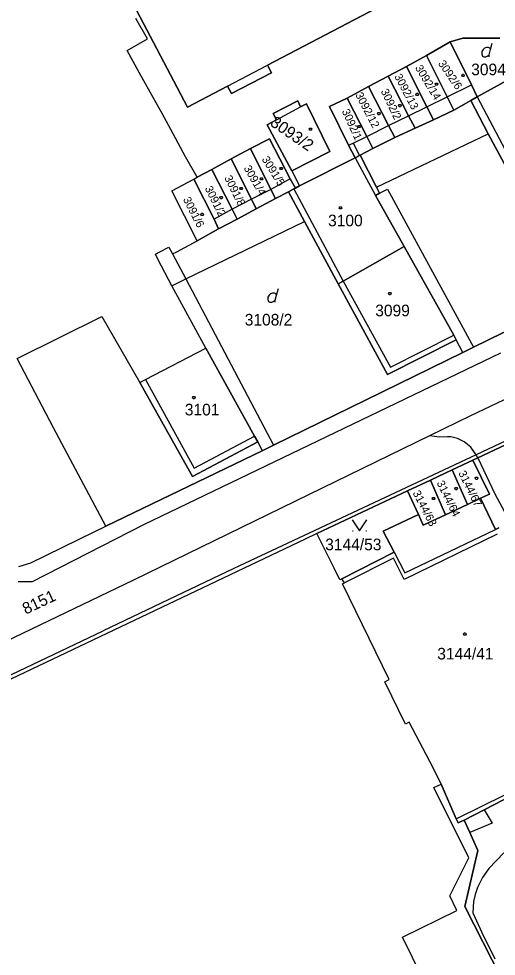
# Model space of a CAD drawing. Extents: x -263587 to -261993, y -1238795 to -1236748.
# Drawn here: x -263095.1 to -263029.4, y -1238503 to -1238374.1 of the extents above; entities that cross this region are included whole.
import ezdxf

# ---------------------------------------------------------------- set-up
doc = ezdxf.new("R2010")
doc.units = 0
doc.layers.add('Vrstva 1', color=7, linetype='Continuous')

msp = doc.modelspace()

# ---------------------------------------------------------------- linework, layer by layer
at = {"layer": 'Vrstva 1'}
for p, q in [((-263079.94, -1238370.91), (-263071.91, -1238386.25)), ((-263071.91, -1238386.25), (-263079.94, -1238370.91)), ((-263060.89, -1238380.49), (-263044.93, -1238372.15)), ((-263044.93, -1238372.15), (-263060.89, -1238380.49)), ((-263077.39, -1238376.88), (-263078.98, -1238374.05)), ((-263080.18, -1238378.46), (-263077.39, -1238376.88)), ((-263035.8, -1238377.26), (-263039.04, -1238379.17)), ((-263039.04, -1238379.17), (-263035.8, -1238377.26)), ((-263035.8, -1238377.26), (-263034.03, -1238376.76)), ((-263034.03, -1238376.76), (-263035.8, -1238377.26)), ((-263032.83, -1238383.17), (-263035.8, -1238377.26)), ((-263035.8, -1238377.26), (-263032.83, -1238383.17)), ((-263034.03, -1238376.76), (-263028.94, -1238376.78)), ((-263028.94, -1238376.78), (-263034.03, -1238376.76)), ((-263078.54, -1238381.47), (-263080.18, -1238378.46)), ((-263030.26, -1238378.34), (-263029.99, -1238377.44)), ((-263039.04, -1238379.17), (-263041.79, -1238380.66)), ((-263041.79, -1238380.66), (-263039.04, -1238379.17)), ((-263039.04, -1238379.17), (-263036.22, -1238384.84)), ((-263036.22, -1238384.84), (-263039.04, -1238379.17)), ((-263066.38, -1238383.36), (-263060.89, -1238380.49)), ((-263060.34, -1238381.53), (-263060.89, -1238380.49)), ((-263060.89, -1238380.49), (-263060.34, -1238381.53)), ((-263041.79, -1238380.66), (-263044.33, -1238382)), ((-263044.33, -1238382), (-263041.79, -1238380.66)), ((-263039, -1238386.21), (-263041.79, -1238380.66)), ((-263041.79, -1238380.66), (-263039, -1238386.21)), ((-263032.07, -1238384.84), (-263024.15, -1238380.47)), ((-263024.15, -1238380.47), (-263032.07, -1238384.84)), ((-263077.04, -1238384.18), (-263078.54, -1238381.47)), ((-263065.83, -1238384.4), (-263060.34, -1238381.53)), ((-263060.34, -1238381.53), (-263065.83, -1238384.4)), ((-263044.33, -1238382), (-263047.02, -1238383.41)), ((-263047.02, -1238383.41), (-263044.33, -1238382)), ((-263041.51, -1238387.44), (-263044.33, -1238382)), ((-263044.33, -1238382), (-263041.51, -1238387.44)), ((-263071.91, -1238386.25), (-263066.38, -1238383.36)), ((-263066.38, -1238383.36), (-263071.91, -1238386.25)), ((-263066.38, -1238383.36), (-263065.83, -1238384.4)), ((-263065.83, -1238384.4), (-263066.38, -1238383.36)), ((-263047.02, -1238383.41), (-263049.93, -1238385.01)), ((-263049.93, -1238385.01), (-263047.02, -1238383.41)), ((-263047.02, -1238383.41), (-263044.26, -1238388.79)), ((-263044.26, -1238388.79), (-263047.02, -1238383.41)), ((-263036.22, -1238384.84), (-263032.83, -1238383.17)), ((-263032.07, -1238384.84), (-263032.83, -1238383.17)), ((-263032.83, -1238383.17), (-263032.07, -1238384.84)), ((-263075.4, -1238387.15), (-263077.04, -1238384.18)), ((-263049.93, -1238385.01), (-263052.38, -1238386.17)), ((-263052.38, -1238386.17), (-263049.93, -1238385.01)), ((-263047.26, -1238390.27), (-263049.93, -1238385.01)), ((-263049.93, -1238385.01), (-263047.26, -1238390.27)), ((-263039, -1238386.21), (-263036.22, -1238384.84)), ((-263036.22, -1238384.84), (-263035.3, -1238386.69)), ((-263035.3, -1238386.69), (-263036.22, -1238384.84)), ((-263032.93, -1238385.36), (-263032.07, -1238384.84)), ((-263032.07, -1238384.84), (-263032.93, -1238385.36)), ((-263032.07, -1238384.84), (-263025.51, -1238397.32)), ((-263060.1, -1238387.14), (-263056.74, -1238385.4)), ((-263056.74, -1238385.4), (-263060.1, -1238387.14)), ((-263059.65, -1238387.98), (-263056.36, -1238386.19)), ((-263056.74, -1238385.4), (-263056.36, -1238386.19)), ((-263056.36, -1238386.19), (-263056.74, -1238385.4)), ((-263056.36, -1238386.19), (-263055.53, -1238385.8)), ((-263055.53, -1238385.8), (-263056.36, -1238386.19)), ((-263055.53, -1238385.8), (-263052.35, -1238392.35)), ((-263052.35, -1238392.35), (-263055.53, -1238385.8)), ((-263052.38, -1238386.17), (-263049.75, -1238391.48)), ((-263049.75, -1238391.48), (-263052.38, -1238386.17)), ((-263041.51, -1238387.44), (-263039, -1238386.21)), ((-263038.1, -1238388.01), (-263039, -1238386.21)), ((-263039, -1238386.21), (-263038.1, -1238388.01)), ((-263035.3, -1238386.69), (-263032.93, -1238385.36)), ((-263032.93, -1238385.36), (-263035.3, -1238386.69)), ((-263032.93, -1238385.36), (-263030.56, -1238389.91)), ((-263030.56, -1238389.91), (-263032.93, -1238385.36)), ((-263073.86, -1238389.91), (-263075.4, -1238387.15)), ((-263059.65, -1238387.98), (-263060.1, -1238387.14)), ((-263060.1, -1238387.14), (-263059.65, -1238387.98)), ((-263044.26, -1238388.79), (-263041.51, -1238387.44)), ((-263040.61, -1238389.16), (-263041.51, -1238387.44)), ((-263041.51, -1238387.44), (-263040.61, -1238389.16)), ((-263038.1, -1238388.01), (-263035.3, -1238386.69)), ((-263035.3, -1238386.69), (-263038.1, -1238388.01)), ((-263060.95, -1238388.67), (-263059.65, -1238387.98)), ((-263059.65, -1238387.98), (-263060.95, -1238388.67)), ((-263057.55, -1238395.02), (-263060.95, -1238388.67)), ((-263060.95, -1238388.67), (-263057.55, -1238395.02)), ((-263047.26, -1238390.27), (-263044.26, -1238388.79)), ((-263044.26, -1238388.79), (-263043.41, -1238390.45)), ((-263043.41, -1238390.45), (-263044.26, -1238388.79)), ((-263040.61, -1238389.16), (-263038.1, -1238388.01)), ((-263038.1, -1238388.01), (-263040.61, -1238389.16)), ((-263072.18, -1238393.07), (-263073.86, -1238389.91)), ((-263045.9, -1238397.25), (-263030.56, -1238389.91)), ((-263043.41, -1238390.45), (-263040.61, -1238389.16)), ((-263040.61, -1238389.16), (-263043.41, -1238390.45)), ((-263030.56, -1238389.91), (-263026.36, -1238397.77)), ((-263026.36, -1238397.77), (-263030.56, -1238389.91)), ((-263060.61, -1238390.6), (-263063.22, -1238391.94)), ((-263063.22, -1238391.94), (-263060.61, -1238390.6)), ((-263057.79, -1238396.13), (-263060.61, -1238390.6)), ((-263060.61, -1238390.6), (-263057.79, -1238396.13)), ((-263049.75, -1238391.48), (-263049.13, -1238391.19)), ((-263049.13, -1238391.19), (-263047.26, -1238390.27)), ((-263049.13, -1238391.19), (-263048.26, -1238392.91)), ((-263046.4, -1238391.96), (-263047.26, -1238390.27)), ((-263047.26, -1238390.27), (-263046.4, -1238391.96)), ((-263046.4, -1238391.96), (-263043.41, -1238390.45)), ((-263043.41, -1238390.45), (-263046.4, -1238391.96)), ((-263063.22, -1238391.94), (-263065.89, -1238393.35)), ((-263065.89, -1238393.35), (-263063.22, -1238391.94)), ((-263060.44, -1238397.56), (-263063.22, -1238391.94)), ((-263063.22, -1238391.94), (-263060.44, -1238397.56)), ((-263052.35, -1238392.35), (-263057.55, -1238395.02)), ((-263057.55, -1238395.02), (-263052.35, -1238392.35)), ((-263049.75, -1238391.48), (-263048.86, -1238393.24)), ((-263048.86, -1238393.24), (-263049.75, -1238391.48)), ((-263048.14, -1238392.85), (-263046.4, -1238391.96)), ((-263046.4, -1238391.96), (-263048.14, -1238392.85)), ((-263070.58, -1238395.89), (-263072.18, -1238393.07)), ((-263065.89, -1238393.35), (-263068.56, -1238394.81)), ((-263068.56, -1238394.81), (-263065.89, -1238393.35)), ((-263065.89, -1238393.35), (-263063.08, -1238398.91)), ((-263063.08, -1238398.91), (-263065.89, -1238393.35)), ((-263056.52, -1238397.07), (-263048.86, -1238393.24)), ((-263048.86, -1238393.24), (-263056.52, -1238397.07)), ((-263048.86, -1238393.24), (-263048.26, -1238392.91)), ((-263048.26, -1238392.91), (-263048.86, -1238393.24)), ((-263048.86, -1238393.24), (-263046.07, -1238398.39)), ((-263048.26, -1238392.91), (-263048.14, -1238392.85)), ((-263048.14, -1238392.85), (-263048.26, -1238392.91)), ((-263045.9, -1238397.25), (-263048.14, -1238392.85)), ((-263048.14, -1238392.85), (-263045.9, -1238397.25)), ((-263068.56, -1238394.81), (-263070.58, -1238395.89)), ((-263070.58, -1238395.89), (-263068.56, -1238394.81)), ((-263065.75, -1238400.3), (-263068.56, -1238394.81)), ((-263068.56, -1238394.81), (-263065.75, -1238400.3)), ((-263057.55, -1238395.02), (-263056.52, -1238397.07)), ((-263074.04, -1238397.77), (-263071.03, -1238396.14)), ((-263071.03, -1238396.14), (-263070.58, -1238395.89)), ((-263071.03, -1238396.14), (-263068.25, -1238401.66)), ((-263068.25, -1238401.66), (-263071.03, -1238396.14)), ((-263057.79, -1238396.13), (-263060.44, -1238397.56)), ((-263057.07, -1238397.39), (-263057.79, -1238396.13)), ((-263057.79, -1238396.13), (-263057.07, -1238397.39)), ((-263070.59, -1238404.62), (-263074.04, -1238397.77)), ((-263060.44, -1238397.56), (-263063.08, -1238398.91)), ((-263059.82, -1238398.8), (-263060.44, -1238397.56)), ((-263060.44, -1238397.56), (-263059.82, -1238398.8)), ((-263059.82, -1238398.8), (-263058.03, -1238397.92)), ((-263058.03, -1238397.92), (-263059.82, -1238398.8)), ((-263058.03, -1238397.92), (-263057.29, -1238397.49)), ((-263057.29, -1238397.49), (-263058.03, -1238397.92)), ((-263058.03, -1238397.92), (-263055.82, -1238402)), ((-263055.82, -1238402), (-263058.03, -1238397.92)), ((-263057.29, -1238397.49), (-263057.07, -1238397.39)), ((-263057.07, -1238397.39), (-263057.29, -1238397.49)), ((-263057.29, -1238397.49), (-263050.48, -1238410.16)), ((-263057.07, -1238397.39), (-263056.52, -1238397.07)), ((-263056.52, -1238397.07), (-263057.07, -1238397.39)), ((-263045.5, -1238398.07), (-263045.9, -1238397.25)), ((-263045.9, -1238397.25), (-263045.5, -1238398.07)), ((-263045.5, -1238398.07), (-263044.4, -1238397.55)), ((-263044.4, -1238397.55), (-263032.6, -1238419.26)), ((-263063.08, -1238398.91), (-263065.75, -1238400.3)), ((-263063.08, -1238398.91), (-263062.47, -1238400.23)), ((-263062.47, -1238400.23), (-263063.08, -1238398.91)), ((-263062.47, -1238400.23), (-263059.82, -1238398.8)), ((-263059.82, -1238398.8), (-263062.47, -1238400.23)), ((-263046.07, -1238398.39), (-263045.5, -1238398.07)), ((-263045.5, -1238398.07), (-263046.07, -1238398.39)), ((-263042.13, -1238405.41), (-263046.07, -1238398.39)), ((-263046.07, -1238398.39), (-263042.13, -1238405.41)), ((-263065.75, -1238400.3), (-263068.25, -1238401.66)), ((-263065.09, -1238401.64), (-263065.75, -1238400.3)), ((-263065.75, -1238400.3), (-263065.09, -1238401.64)), ((-263065.09, -1238401.64), (-263062.47, -1238400.23)), ((-263062.47, -1238400.23), (-263065.09, -1238401.64)), ((-263068.25, -1238401.66), (-263067.63, -1238403)), ((-263067.63, -1238403), (-263068.25, -1238401.66)), ((-263067.63, -1238403), (-263065.09, -1238401.64)), ((-263065.09, -1238401.64), (-263067.63, -1238403)), ((-263072.15, -1238409.87), (-263055.82, -1238402)), ((-263070.59, -1238404.62), (-263067.63, -1238403)), ((-263067.63, -1238403), (-263070.59, -1238404.62)), ((-263055.82, -1238402), (-263051.2, -1238410.54)), ((-263051.2, -1238410.54), (-263055.82, -1238402)), ((-263075.69, -1238406.13), (-263074.48, -1238405.5)), ((-263074.48, -1238405.5), (-263073.94, -1238406.44)), ((-263073.36, -1238406.14), (-263070.59, -1238404.62)), ((-263042.13, -1238405.41), (-263050.48, -1238410.16)), ((-263050.48, -1238410.16), (-263042.13, -1238405.41)), ((-263035.3, -1238417.59), (-263042.13, -1238405.41)), ((-263042.13, -1238405.41), (-263035.3, -1238417.59)), ((-263076.28, -1238406.49), (-263075.69, -1238406.13)), ((-263075.91, -1238407.23), (-263076.28, -1238406.49)), ((-263073.94, -1238406.44), (-263073.36, -1238406.14)), ((-263073.94, -1238406.44), (-263072.15, -1238409.87)), ((-263074.05, -1238410.83), (-263075.91, -1238407.23)), ((-263009.51, -1238407.99), (-263032.6, -1238419.26)), ((-263032.6, -1238419.26), (-263009.51, -1238407.99)), ((-263074.05, -1238410.83), (-263072.15, -1238409.87)), ((-263072.15, -1238409.87), (-263060.09, -1238432.72)), ((-263050.48, -1238410.16), (-263051.2, -1238410.54)), ((-263051.2, -1238410.54), (-263050.48, -1238410.16)), ((-263051.2, -1238410.54), (-263044.42, -1238423.03)), ((-263044.42, -1238423.03), (-263051.2, -1238410.54)), ((-263050.48, -1238410.16), (-263043.99, -1238421.99)), ((-263069.38, -1238419.39), (-263074.05, -1238410.83)), ((-263059.67, -1238412.09), (-263059.4, -1238411.19)), ((-263095.34, -1238420.82), (-263083.68, -1238415.06)), ((-263083.68, -1238415.06), (-263078.47, -1238424.12)), ((-263044.42, -1238423.03), (-263034.94, -1238418.24)), ((-263034.94, -1238418.24), (-263044.42, -1238423.03)), ((-263043.99, -1238421.99), (-263035.3, -1238417.59)), ((-263034.94, -1238418.24), (-263035.3, -1238417.59)), ((-263035.3, -1238417.59), (-263034.94, -1238418.24)), ((-263034.05, -1238420), (-263034.94, -1238418.24)), ((-263077.67, -1238423.72), (-263069.38, -1238419.39)), ((-263062.69, -1238431.48), (-263069.38, -1238419.39)), ((-263069.38, -1238419.39), (-263062.69, -1238431.48)), ((-263032.6, -1238419.26), (-263034.05, -1238420)), ((-263034.05, -1238420), (-263032.6, -1238419.26)), ((-263090.32, -1238430.33), (-263095.34, -1238420.82)), ((-263028.88, -1238420.08), (-263077.95, -1238443.69)), ((-263034.05, -1238420), (-263047.32, -1238426.49)), ((-263047.32, -1238426.49), (-263034.05, -1238420)), ((-263078.47, -1238424.12), (-263077.67, -1238423.72)), ((-263078.47, -1238424.12), (-263071.21, -1238437.03)), ((-263071.21, -1238437.03), (-263078.47, -1238424.12)), ((-263077.67, -1238423.72), (-263070.96, -1238435.89)), ((-263026.6, -1238425.67), (-263033.01, -1238428.71)), ((-263047.32, -1238426.49), (-263060.09, -1238432.72)), ((-263060.09, -1238432.72), (-263047.32, -1238426.49)), ((-263033.01, -1238428.71), (-263038.64, -1238431.46)), ((-263083.13, -1238443.86), (-263090.32, -1238430.33)), ((-263038.64, -1238431.46), (-263079.32, -1238451.28)), ((-263071.21, -1238437.03), (-263062.25, -1238432.28)), ((-263062.25, -1238432.28), (-263071.21, -1238437.03)), ((-263070.96, -1238435.89), (-263062.69, -1238431.48)), ((-263062.25, -1238432.28), (-263062.69, -1238431.48)), ((-263062.69, -1238431.48), (-263062.25, -1238432.28)), ((-263062.25, -1238432.28), (-263061.65, -1238433.5)), ((-263060.09, -1238432.72), (-263061.65, -1238433.5)), ((-263061.65, -1238433.5), (-263060.09, -1238432.72)), ((-263037.27, -1238431.63), (-263038.64, -1238431.46)), ((-263036.16, -1238431.58), (-263037.27, -1238431.63)), ((-263035.7, -1238431.6), (-263036.16, -1238431.58)), ((-263034.78, -1238431.81), (-263035.7, -1238431.6)), ((-263033.88, -1238432.25), (-263034.78, -1238431.81)), ((-263032.94, -1238433.01), (-263033.88, -1238432.25)), ((-263027.35, -1238431.78), (-263032.2, -1238434.06)), ((-263027.39, -1238432.34), (-263032, -1238434.48)), ((-263032, -1238434.48), (-263027.39, -1238432.34)), ((-263061.65, -1238433.5), (-263083.13, -1238443.86)), ((-263083.13, -1238443.86), (-263061.65, -1238433.5)), ((-263032.2, -1238434.06), (-263032.94, -1238433.01)), ((-263032.2, -1238434.06), (-263065.54, -1238449.71)), ((-263035.52, -1238436.14), (-263032.65, -1238434.78)), ((-263032.65, -1238434.78), (-263035.52, -1238436.14)), ((-263032, -1238434.48), (-263032.65, -1238434.78)), ((-263032.65, -1238434.78), (-263032, -1238434.48)), ((-263032.65, -1238434.78), (-263030.37, -1238439.45)), ((-263030.37, -1238439.45), (-263032.65, -1238434.78)), ((-263032, -1238434.48), (-263032.2, -1238434.06)), ((-263032, -1238434.48), (-263029.63, -1238439.4)), ((-263038.51, -1238437.53), (-263035.52, -1238436.14)), ((-263035.52, -1238436.14), (-263038.51, -1238437.53)), ((-263033.39, -1238440.87), (-263035.52, -1238436.14)), ((-263035.52, -1238436.14), (-263033.39, -1238440.87)), ((-263041.63, -1238439.03), (-263038.51, -1238437.53)), ((-263038.51, -1238437.53), (-263041.63, -1238439.03)), ((-263036.44, -1238442.31), (-263038.51, -1238437.53)), ((-263038.51, -1238437.53), (-263036.44, -1238442.31)), ((-263054.1, -1238444.88), (-263041.63, -1238439.03)), ((-263041.63, -1238439.03), (-263054.1, -1238444.88)), ((-263040.16, -1238442.27), (-263041.63, -1238439.03)), ((-263041.63, -1238439.03), (-263040.16, -1238442.27)), ((-263031.61, -1238440.03), (-263033.39, -1238440.87)), ((-263033.39, -1238440.87), (-263031.61, -1238440.03)), ((-263030.37, -1238439.45), (-263031.61, -1238440.03)), ((-263031.61, -1238440.03), (-263030.37, -1238439.45)), ((-263031.61, -1238440.03), (-263029.55, -1238444.33)), ((-263029.55, -1238444.33), (-263031.61, -1238440.03)), ((-263029.63, -1238439.4), (-263015.83, -1238465.48)), ((-263033.39, -1238440.87), (-263036.44, -1238442.31)), ((-263036.44, -1238442.31), (-263033.39, -1238440.87)), ((-263040.16, -1238442.27), (-263045.01, -1238444.54)), ((-263045.01, -1238444.54), (-263040.16, -1238442.27)), ((-263039.49, -1238443.75), (-263040.16, -1238442.27)), ((-263040.16, -1238442.27), (-263039.49, -1238443.75)), ((-263036.44, -1238442.31), (-263039.49, -1238443.75)), ((-263039.49, -1238443.75), (-263036.44, -1238442.31)), ((-263077.95, -1238443.69), (-263093.27, -1238451.5)), ((-263084.73, -1238444.64), (-263083.13, -1238443.86)), ((-263029.55, -1238444.33), (-263029.08, -1238444.1)), ((-263029.08, -1238444.1), (-263029.55, -1238444.33)), ((-263093.44, -1238448.92), (-263084.73, -1238444.64)), ((-263054.1, -1238444.88), (-263055.73, -1238445.65)), ((-263051.74, -1238449.65), (-263054.1, -1238444.88)), ((-263049.2, -1238444.52), (-263049.1, -1238444.52)), ((-263047.4, -1238444.52), (-263047.3, -1238444.52)), ((-263045.01, -1238444.54), (-263043.49, -1238447.45)), ((-263043.49, -1238447.45), (-263045.01, -1238444.54)), ((-263029.33, -1238444.95), (-263042.11, -1238451.22)), ((-263042, -1238450.3), (-263029.55, -1238444.33)), ((-263055.73, -1238445.65), (-263108.72, -1238470.85)), ((-263043.49, -1238447.45), (-263050.66, -1238451.1)), ((-263050.66, -1238451.1), (-263043.49, -1238447.45)), ((-263043.49, -1238447.45), (-263042, -1238450.3)), ((-263095.11, -1238449.43), (-263093.44, -1238448.92)), ((-263043.57, -1238448.28), (-263050.31, -1238451.68)), ((-263042.11, -1238451.22), (-263043.57, -1238448.28)), ((-263065.54, -1238449.71), (-263083.48, -1238458.24)), ((-263050.96, -1238451.25), (-263051.74, -1238449.65)), ((-263079.32, -1238451.28), (-263125.04, -1238473.29)), ((-263093.27, -1238451.5), (-263095.19, -1238451.53)), ((-263050.66, -1238451.1), (-263050.96, -1238451.25)), ((-263050.31, -1238451.68), (-263050.66, -1238451.1)), ((-263050.57, -1238451.79), (-263050.31, -1238451.68)), ((-263044.15, -1238464.94), (-263050.57, -1238451.79)), ((-263108.96, -1238470.41), (-263083.48, -1238458.24)), ((-263044.75, -1238465.28), (-263044.15, -1238464.94)), ((-263041.93, -1238471.08), (-263044.75, -1238465.28)), ((-263041.43, -1238470.82), (-263041.93, -1238471.08)), ((-263038.12, -1238477.11), (-263041.43, -1238470.82)), ((-263037.03, -1238479.33), (-263038.12, -1238477.11)), ((-263038.01, -1238479.81), (-263037.03, -1238479.33)), ((-263033.21, -1238489.48), (-263038.01, -1238479.81)), ((-263034.96, -1238484.09), (-263037.03, -1238479.33)), ((-263037.03, -1238479.33), (-263034.96, -1238484.09)), ((-263034.96, -1238484.09), (-263028.19, -1238480.77)), ((-263027.2, -1238480.85), (-263031.09, -1238482.85)), ((-263031.09, -1238482.85), (-263027.2, -1238480.85)), ((-263031.09, -1238482.85), (-263033.87, -1238484.27)), ((-263033.87, -1238484.27), (-263031.09, -1238482.85)), ((-263031.09, -1238482.85), (-263030.03, -1238484.71)), ((-263034.68, -1238484.65), (-263034.96, -1238484.09)), ((-263034.96, -1238484.09), (-263034.68, -1238484.65)), ((-263033.87, -1238484.27), (-263034.52, -1238484.59)), ((-263034.52, -1238484.59), (-263033.87, -1238484.27)), ((-263033.87, -1238484.27), (-263033.08, -1238486.01)), ((-263033.08, -1238486.01), (-263033.87, -1238484.27)), ((-263034.52, -1238484.59), (-263034.68, -1238484.65)), ((-263034.68, -1238484.65), (-263034.52, -1238484.59)), ((-263030.03, -1238484.71), (-263033.08, -1238486.01)), ((-263033.08, -1238486.01), (-263031.96, -1238488.46)), ((-263031.96, -1238488.46), (-263033.08, -1238486.01)), ((-263031.96, -1238488.46), (-263033.76, -1238496.15)), ((-263033.76, -1238496.15), (-263031.96, -1238488.46)), ((-263028.41, -1238488.79), (-263030.47, -1238490.94)), ((-263035.85, -1238494.71), (-263033.21, -1238489.48)), ((-263030.47, -1238490.94), (-263031.35, -1238492.18)), ((-263031.35, -1238492.18), (-263032.02, -1238493.53)), ((-263032.36, -1238494.5), (-263032.59, -1238495.49)), ((-263032.02, -1238493.53), (-263032.36, -1238494.5)), ((-263034.87, -1238496.72), (-263035.85, -1238494.71)), ((-263032.59, -1238495.49), (-263032.69, -1238497.05)), ((-263042.35, -1238500.36), (-263034.87, -1238496.72)), ((-263033.76, -1238496.15), (-263026.65, -1238510.12)), ((-263026.65, -1238510.12), (-263033.76, -1238496.15)), ((-263032.69, -1238497.05), (-263031.44, -1238499.76)), ((-263034.75, -1238515.65), (-263042.35, -1238500.36)), ((-263031.44, -1238499.76), (-263029.65, -1238503.37))]:
    msp.add_line(p, q, dxfattribs=at)
for points in [[(-263030.44, -1238379.33), (-263030.44, -1238379.06), (-263030.26, -1238378.34), (-263030.35, -1238378.16), (-263030.53, -1238378.07), (-263030.8, -1238378.07), (-263031.07, -1238378.16), (-263031.25, -1238378.34), (-263031.43, -1238378.61), (-263031.43, -1238378.97), (-263031.34, -1238379.24), (-263031.16, -1238379.33), (-263030.89, -1238379.33), (-263030.71, -1238379.24), (-263030.44, -1238379.06)], [(-263059.85, -1238413.08), (-263059.85, -1238412.81), (-263059.67, -1238412.09), (-263059.76, -1238411.91), (-263059.94, -1238411.82), (-263060.21, -1238411.82), (-263060.48, -1238411.91), (-263060.66, -1238412.09), (-263060.84, -1238412.36), (-263060.84, -1238412.72), (-263060.75, -1238412.99), (-263060.57, -1238413.08), (-263060.3, -1238413.08), (-263060.12, -1238412.99), (-263059.85, -1238412.81)], [(-263049.25, -1238443.02), (-263048.25, -1238444.52), (-263047.25, -1238443.02)]]:
    msp.add_lwpolyline(points, dxfattribs=at)
for points in [[(-263033.93, -1238381.74), (-263033.84, -1238381.89), (-263033.93, -1238382.04), (-263034.11, -1238382.04), (-263034.2, -1238381.89), (-263034.11, -1238381.74)], [(-263037.56, -1238382.94), (-263037.47, -1238383.09), (-263037.56, -1238383.24), (-263037.74, -1238383.24), (-263037.83, -1238383.09), (-263037.74, -1238382.94)], [(-263040.25, -1238384.35), (-263040.16, -1238384.5), (-263040.25, -1238384.65), (-263040.43, -1238384.65), (-263040.52, -1238384.5), (-263040.43, -1238384.35)], [(-263042.6, -1238385.89), (-263042.51, -1238386.04), (-263042.6, -1238386.19), (-263042.78, -1238386.19), (-263042.87, -1238386.04), (-263042.78, -1238385.89)], [(-263045.52, -1238387), (-263045.43, -1238387.15), (-263045.52, -1238387.3), (-263045.7, -1238387.3), (-263045.79, -1238387.15), (-263045.7, -1238387)], [(-263048.21, -1238388.76), (-263048.12, -1238388.91), (-263048.21, -1238389.06), (-263048.39, -1238389.06), (-263048.48, -1238388.91), (-263048.39, -1238388.76)], [(-263054.91, -1238389.13), (-263054.82, -1238389.28), (-263054.91, -1238389.43), (-263055.09, -1238389.43), (-263055.18, -1238389.28), (-263055.09, -1238389.13)], [(-263058.93, -1238394.53), (-263058.84, -1238394.68), (-263058.93, -1238394.83), (-263059.11, -1238394.83), (-263059.2, -1238394.68), (-263059.11, -1238394.53)], [(-263061.64, -1238395.96), (-263061.55, -1238396.11), (-263061.64, -1238396.26), (-263061.82, -1238396.26), (-263061.91, -1238396.11), (-263061.82, -1238395.96)], [(-263064.42, -1238397.3), (-263064.33, -1238397.45), (-263064.42, -1238397.6), (-263064.6, -1238397.6), (-263064.69, -1238397.45), (-263064.6, -1238397.3)], [(-263067.18, -1238398.55), (-263067.09, -1238398.7), (-263067.18, -1238398.85), (-263067.36, -1238398.85), (-263067.45, -1238398.7), (-263067.36, -1238398.55)], [(-263050.79, -1238399.94), (-263050.7, -1238400.09), (-263050.79, -1238400.24), (-263050.97, -1238400.24), (-263051.06, -1238400.09), (-263050.97, -1238399.94)], [(-263069.78, -1238400.85), (-263069.69, -1238401), (-263069.78, -1238401.15), (-263069.96, -1238401.15), (-263070.05, -1238401), (-263069.96, -1238400.85)], [(-263043.99, -1238411.74), (-263043.9, -1238411.89), (-263043.99, -1238412.04), (-263044.17, -1238412.04), (-263044.26, -1238411.89), (-263044.17, -1238411.74)], [(-263070.94, -1238426.04), (-263070.85, -1238426.19), (-263070.94, -1238426.34), (-263071.12, -1238426.34), (-263071.21, -1238426.19), (-263071.12, -1238426.04)], [(-263032.08, -1238437.14), (-263031.99, -1238437.29), (-263032.08, -1238437.44), (-263032.26, -1238437.44), (-263032.35, -1238437.29), (-263032.26, -1238437.14)], [(-263034.89, -1238438.56), (-263034.8, -1238438.71), (-263034.89, -1238438.86), (-263035.07, -1238438.86), (-263035.16, -1238438.71), (-263035.07, -1238438.56)], [(-263037.99, -1238439.92), (-263037.9, -1238440.07), (-263037.99, -1238440.22), (-263038.17, -1238440.22), (-263038.26, -1238440.07), (-263038.17, -1238439.92)], [(-263033.68, -1238458.55), (-263033.59, -1238458.7), (-263033.68, -1238458.85), (-263033.86, -1238458.85), (-263033.95, -1238458.7), (-263033.86, -1238458.55)]]:
    msp.add_lwpolyline(points, close=True, dxfattribs=at)

# ---------------------------------------------------------------- texts
for s, height, rotation, p in [('3092/6', 1.1, 304.46977, (-263037.494, -1238380.253)), ('3092/14', 1.1, 300.91743, (-263040.647, -1238380.839)), ('3092/13', 1.1, 297.65157, (-263043.495, -1238382.009)), ('3092/2', 1.1, 295.30245, (-263045.355, -1238384.037)), ('3092/12', 1.1, 297.65157, (-263048.865, -1238384.549)), ('3093/2', 1.6, 325.55462, (-263060.659, -1238388.69)), ('3092/1', 1.1, 294.44301, (-263050.709, -1238386.802)), ('3091/5', 1.1, 302.00605, (-263061.734, -1238393.415)), ('3091/4', 1.1, 299.71422, (-263064.208, -1238394.635)), ('3091/8', 1.1, 296.56296, (-263066.872, -1238395.965)), ('3091/2', 1.1, 296.56296, (-263069.552, -1238397.415)), ('3091/6', 1.1, 297.02132, (-263072.55, -1238398.925)), ('3144/67', 1.1, 296.16188, (-263034.688, -1238436.557)), ('3144/64', 1.1, 296.04729, (-263037.673, -1238437.912)), ('3144/63', 1.1, 297.19321, (-263040.968, -1238439.289)), ('8151', 1.6, 25.43933, (-263094.137, -1238456.049))]:
    msp.add_text(s, height=height, rotation=rotation, dxfattribs=at).set_placement(p)
for s, p in [('3094', (-263032.893, -1238381.87)), ('3100', (-263052.573, -1238402.64)), ('3099', (-263046.09, -1238415.01)), ('3108/2', (-263064.029, -1238416.28)), ('3101', (-263072.264, -1238428.64)), ('3144/53', (-263052.968, -1238447.18)), ('3144/41', (-263037.559, -1238462.2))]:
    msp.add_text(s, height=1.6, dxfattribs=at).set_placement(p)

doc.saveas('drawing.dxf')
